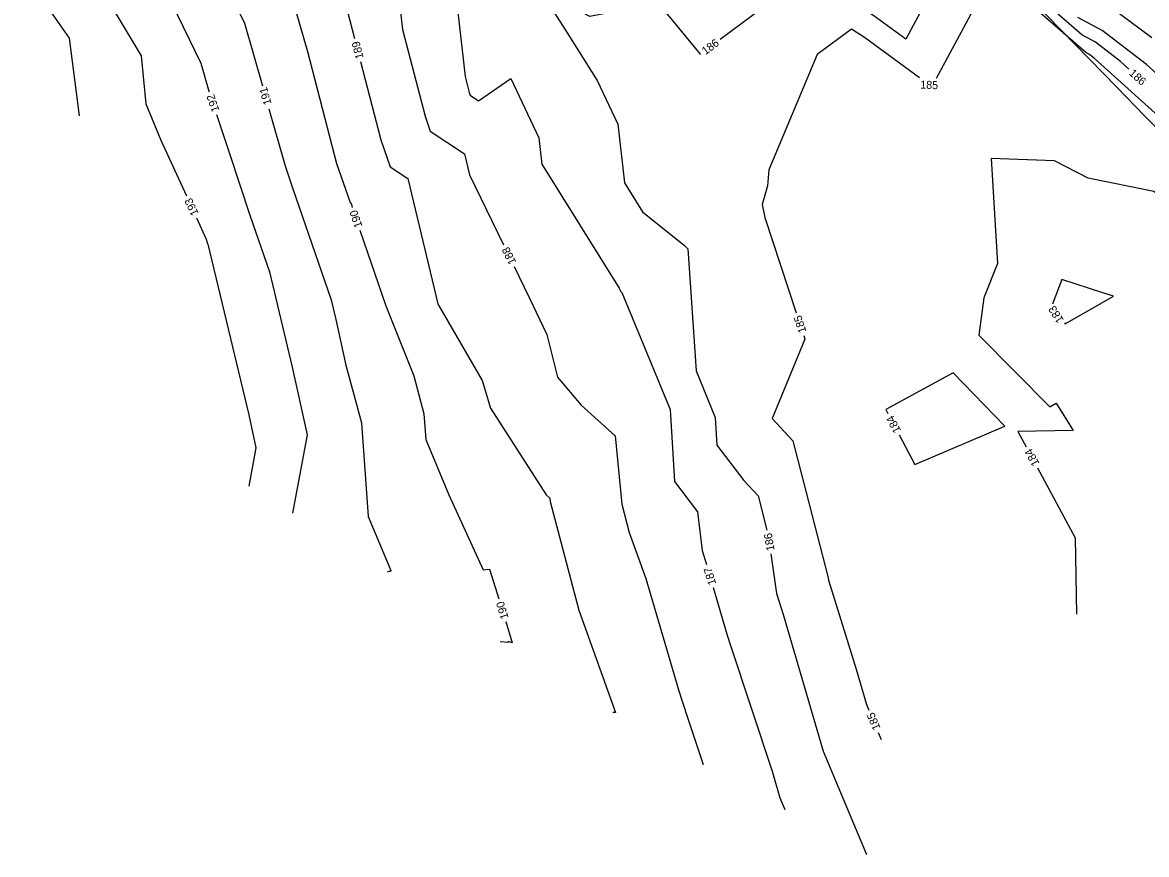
# Model space of a CAD drawing. Extents: x 2086416 to 2115205, y 575507 to 632762.
# Drawn here: x 2110178.9 to 2110459.9, y 581656.9 to 581864.8 of the extents above; entities that cross this region are included whole.
import ezdxf

# ---------------------------------------------------------------- set-up
doc = ezdxf.new("R2010")
doc.units = 0
for name, color, linetype in [('DTM Contours Major', 7, 'Continuous'), ('DTM Contours Major Text', 7, 'Continuous'), ('DTM Contours Minor', 7, 'Continuous'), ('DTM Contours Minor Text', 7, 'Continuous'), ('Exist Hydrographic FEMA Cross Section', 7, 'Continuous')]:
    doc.layers.add(name, color=color, linetype=linetype)

msp = doc.modelspace()

# ---------------------------------------------------------------- linework, layer by layer
at = {"layer": 'DTM Contours Major'}
for points in [[(2110369.37, 581922.2), (2110372.5, 581918.84), (2110375.41, 581915.72), (2110377.65, 581904.64), (2110390.4, 581892.7), (2110397.79, 581891.94), (2110416.83, 581876.68), (2110419.88, 581874.24), (2110407.25, 581850.79)], [(2110253.22, 581913.88), (2110242.42, 581880.48), (2110245.25, 581874.66), (2110250.14, 581857.58), (2110257.38, 581829.58), (2110260.82, 581819.81), (2110261.06, 581819.65), (2110261.31, 581818.59)], [(2110477.66, 581830.47), (2110467.52, 581837.44), (2110466.26, 581838.39), (2110465.28, 581839.19), (2110446.86, 581855.82), (2110445.45, 581856.9), (2110444.68, 581857.31), (2110425.22, 581874.31), (2110424.26, 581875.03), (2110421.59, 581877.72), (2110420.54, 581878.96), (2110417.81, 581883.75), (2110405.43, 581897.24), (2110404.4, 581897.68)], [(2110403.16, 581850.97), (2110389.35, 581861.02), (2110386.08, 581863.1), (2110377.56, 581856.78), (2110365.48, 581827.95), (2110365.13, 581823.98), (2110363.82, 581819.31), (2110364.47, 581816.05), (2110372.29, 581792.29)], [(2110263.2, 581812.89), (2110269.7, 581793.97), (2110276.69, 581776.53), (2110279.24, 581766.99), (2110279.72, 581760.61), (2110285.47, 581746.75), (2110294.07, 581728.05), (2110295.66, 581728.24), (2110297.93, 581720.83)], [(2110374.17, 581786.59), (2110374.48, 581785.64), (2110366.28, 581765.86), (2110371.48, 581760.29), (2110380.21, 581726.38), (2110380.34, 581725.48), (2110387.29, 581703.26), (2110389.89, 581694.37), (2110390.47, 581692.99)], [(2110299.7, 581715.1), (2110301.31, 581709.84), (2110300.26, 581710.15), (2110300.23, 581709.91), (2110298.48, 581710.03), (2110298.27, 581709.94)], [(2110392.78, 581687.45), (2110393.54, 581685.63)]]:
    msp.add_lwpolyline(points, dxfattribs=at)
at = {"layer": 'DTM Contours Minor'}
for points in [[(2110301.63, 581975.45), (2110302.04, 581974.77), (2110310.59, 581959.81), (2110285.87, 581958.31), (2110269.33, 581957.31), (2110265.53, 581957.76), (2110258.51, 581958.57), (2110218.92, 581909.52), (2110215.63, 581898.75), (2110210.19, 581881.92), (2110223.48, 581854.62), (2110225.48, 581847.63), (2110225.52, 581847.51)], [(2110277.9, 581972.3), (2110273.06, 581972), (2110267.58, 581972.65), (2110257.47, 581973.82), (2110200.42, 581903.14), (2110195.69, 581887.62), (2110194.08, 581882.65), (2110199.28, 581871.96), (2110208.59, 581856.5), (2110209.7, 581844.49), (2110213.48, 581835.41), (2110219.86, 581821.45)], [(2110305.75, 581973.35), (2110317.27, 581953.18), (2110317.3, 581953.14), (2110318.49, 581952.03), (2110321.38, 581945.99), (2110310.24, 581946.03), (2110302.75, 581944.87), (2110274.84, 581943.18), (2110265.6, 581942.62), (2110263.47, 581942.87), (2110259.55, 581943.32), (2110237.41, 581915.9), (2110235.58, 581909.87), (2110226.31, 581881.2), (2110234.36, 581864.64), (2110238.85, 581848.99)], [(2110310.4, 581975.13), (2110311.78, 581972.92), (2110319.5, 581959.4), (2110319.67, 581959.11), (2110326.46, 581952.81), (2110336.26, 581932.33), (2110337.91, 581930.13), (2110342.94, 581918.36), (2110327.45, 581919.35), (2110326.2, 581920.21), (2110297.45, 581918.49), (2110279.39, 581918.55), (2110267.52, 581916.71), (2110261.26, 581895.57), (2110257.09, 581881.5), (2110257.62, 581880.73), (2110258.31, 581874.72), (2110261.9, 581860.82)], [(2110328.29, 581963.38), (2110338.41, 581953.97), (2110340.59, 581949.41), (2110349.17, 581938.01), (2110353.6, 581927.66), (2110366.24, 581914.12), (2110368.17, 581912.04), (2110373.36, 581886.45), (2110376.29, 581883.71), (2110395.58, 581881.74), (2110404.88, 581874.28), (2110406.37, 581873.09), (2110399.68, 581860.65), (2110391.46, 581866.63), (2110375.29, 581876.92), (2110353.26, 581860.55)], [(2110461.2, 581860.98), (2110453.09, 581866.98), (2110452.51, 581871.6), (2110446.72, 581867.73), (2110441.77, 581870.37), (2110440.33, 581871.63), (2110429.34, 581879.87), (2110429.12, 581880.09), (2110418.51, 581892.57), (2110417.49, 581894.37), (2110411.18, 581902.8), (2110409.45, 581903.54), (2110401.98, 581913.11), (2110400.39, 581915.69), (2110390.83, 581924.76), (2110388.22, 581926.24), (2110387.12, 581927.06), (2110384.59, 581928.99)], [(2110347.71, 581918.62), (2110353.65, 581904.72), (2110353.7, 581904.68), (2110353.7, 581904.67), (2110353.73, 581904.55), (2110353.54, 581904.51), (2110353.43, 581904.57), (2110316.59, 581906.92), (2110313.59, 581908.97), (2110276.62, 581906.77), (2110270.04, 581884.58), (2110271.75, 581882.11), (2110273.92, 581863.02), (2110279.51, 581841.39), (2110280.82, 581837.67), (2110289.39, 581831.97), (2110290.63, 581826.76), (2110299.16, 581809.22)], [(2110185.22, 581900.84), (2110181.93, 581896.76), (2110178.88, 581886.78), (2110181.8, 581873.46), (2110190.57, 581860.89), (2110193.02, 581841.51)], [(2110288.13, 581896.97), (2110285.71, 581896.82), (2110283, 581887.65), (2110285.87, 581883.5), (2110289.54, 581851.33), (2110290.58, 581847.3), (2110290.82, 581846.6), (2110292.92, 581845.21), (2110300.94, 581850.81), (2110307.98, 581835.94), (2110308.72, 581829.44), (2110328.04, 581798.41), (2110328.28, 581797.91), (2110328.33, 581797.81), (2110328.36, 581797.69), (2110328.67, 581797.32), (2110340.79, 581768.09), (2110341.88, 581750.11), (2110347.64, 581742.54), (2110348.83, 581732.84), (2110349.85, 581729.37)], [(2110348.44, 581856.97), (2110348.37, 581856.91), (2110337.84, 581869.61), (2110320.7, 581866.27), (2110308.32, 581872.89), (2110315.01, 581862.24), (2110322.51, 581850.28), (2110327.68, 581839.37), (2110329.34, 581824.75), (2110333.87, 581817.46), (2110344.38, 581809.08), (2110345.17, 581808.24), (2110347.25, 581777.74), (2110352.06, 581766.14), (2110352.48, 581759.21), (2110359.23, 581750.34), (2110362.78, 581746.53), (2110364.99, 581737.98)], [(2110455.48, 581853.14), (2110453.36, 581855.05), (2110447.12, 581859.84), (2110443.71, 581861.67), (2110430.26, 581873.42)], [(2110465.2, 581849.45), (2110459.85, 581854.28), (2110448.78, 581862.79), (2110442.74, 581866.02)], [(2110263.4, 581855.01), (2110268.44, 581835.49), (2110270.82, 581828.74), (2110275.22, 581825.81), (2110282.69, 581794.52), (2110282.77, 581794.34), (2110282.85, 581794.18), (2110293.82, 581775.31), (2110295.89, 581768.48), (2110309.77, 581746.75), (2110310.69, 581745.93), (2110310.76, 581745.16), (2110317.97, 581717.95), (2110327.13, 581692.38), (2110326.53, 581692.42), (2110326.49, 581692.4)], [(2110240.5, 581843.22), (2110244.57, 581828.98), (2110245.5, 581826.22), (2110246.4, 581823.47), (2110256.06, 581795.5), (2110257.23, 581790.62), (2110259.73, 581779.19), (2110263.59, 581764.77), (2110265.33, 581741.41), (2110270.94, 581727.87), (2110270.91, 581727.61), (2110270.43, 581727.64), (2110270.06, 581727.47)], [(2110227.42, 581841.82), (2110230.67, 581832.1), (2110235.74, 581816.62), (2110240.62, 581802.48), (2110246.33, 581778.69), (2110250.03, 581761.79), (2110246.42, 581742.17)], [(2110512.45, 581799.94), (2110493.85, 581798.28), (2110491.61, 581798.98), (2110486.39, 581800.61), (2110477.44, 581810.98), (2110475.99, 581811.48), (2110461.73, 581822.53), (2110445.25, 581825.89), (2110436.87, 581830.21), (2110421.03, 581830.82), (2110422.59, 581804.61), (2110419.24, 581796.01), (2110417.96, 581786.65), (2110435.66, 581768.75), (2110437.3, 581769.68), (2110441.51, 581762.84), (2110427.74, 581762.65), (2110429.81, 581758.8)], [(2110222.35, 581815.99), (2110224.8, 581810.63), (2110225.08, 581809.76), (2110225.19, 581809.45), (2110235.43, 581766.76), (2110237.23, 581758.53), (2110235.48, 581748.98)], [(2110301.78, 581803.83), (2110305.53, 581796.12), (2110309.95, 581786.81), (2110312.65, 581776.15), (2110318.53, 581769.15), (2110327.05, 581761.53), (2110328.7, 581744.46), (2110330.58, 581737.39), (2110334.7, 581725.87), (2110342.92, 581697.83), (2110345.05, 581691.4), (2110349, 581679.45)], [(2110451.6, 581796.4), (2110448.92, 581797.27), (2110438.73, 581800.62), (2110436.42, 581794.69), (2110436.39, 581794.44)], [(2110439.33, 581789.74), (2110439.53, 581789.54), (2110451.6, 581796.4)], [(2110424.41, 581763.97), (2110411.51, 581777.24), (2110394.67, 581768.08), (2110395.2, 581767.07)], [(2110398.01, 581761.76), (2110401.92, 581754.37), (2110424.41, 581763.97)], [(2110432.64, 581753.51), (2110442, 581736.02), (2110442.4, 581716.95)], [(2110365.97, 581732.06), (2110367.4, 581722.15), (2110369.12, 581716.67), (2110379.05, 581682.73), (2110389.83, 581656.93)], [(2110351.54, 581723.61), (2110355.03, 581711.72), (2110355.88, 581709.13), (2110366.25, 581677.78), (2110368.21, 581671.09), (2110369.42, 581668.18)]]:
    msp.add_lwpolyline(points, dxfattribs=at)
at = {"layer": 'Exist Hydrographic FEMA Cross Section'}
msp.add_lwpolyline([(2110466.33, 581834.4), (2110459.39, 581841.51), (2110452.45, 581848.62), (2110445.51, 581855.74), (2110438.57, 581862.85), (2110431.63, 581869.96)], dxfattribs=at)

# ---------------------------------------------------------------- texts
at = {"layer": 'DTM Contours Major Text'}
for s, rotation, p in [('185', 357.4395, (2110403.27, 581848.31)), ('190', 108.3676, (2110263.89, 581813.89)), ('185', 108.2264, (2110374.89, 581787.59)), ('190', 107.0941, (2110300.44, 581716.08)), ('185', 112.6798, (2110393.42, 581688.51))]:
    msp.add_text(s, height=2, rotation=rotation, dxfattribs=at).set_placement(p)
at = {"layer": 'DTM Contours Minor Text'}
for s, rotation, p in [('186', 36.605, (2110349.62, 581856.6)), ('189', 104.4886, (2110264.19, 581855.96)), ('186', 317.9204, (2110455.34, 581851.91)), ('192', 108.4618, (2110228.14, 581842.82)), ('191', 105.9786, (2110241.17, 581844.52)), ('193', 114.5362, (2110222.96, 581817.06)), ('188', 115.93, (2110302.36, 581804.91)), ('183', 122.0606, (2110439.27, 581790.48)), ('184', 117.8676, (2110398.55, 581762.87)), ('184', 118.1687, (2110433.18, 581754.62)), ('186', 99.4693, (2110366.9, 581732.95)), ('187', 106.3462, (2110352.3, 581724.58))]:
    msp.add_text(s, height=2, rotation=rotation, dxfattribs=at).set_placement(p)

doc.saveas('drawing.dxf')
